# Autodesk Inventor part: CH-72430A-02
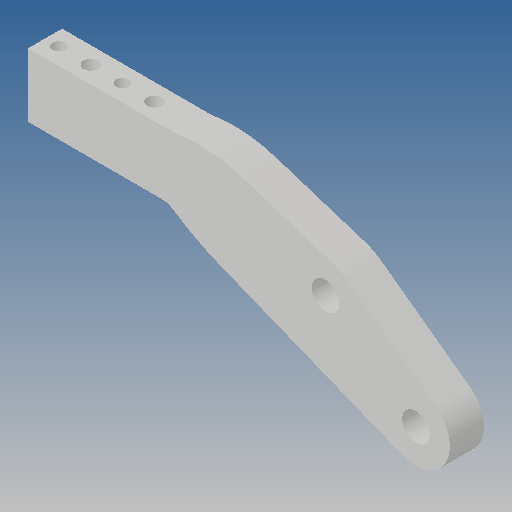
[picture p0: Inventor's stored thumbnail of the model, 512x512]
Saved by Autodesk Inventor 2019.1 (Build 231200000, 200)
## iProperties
Created: 2012-10
Part Number: CH-72430A-02
Material: Ogólny
Document SubType Name: Modeling
Designer: CADENGINEERING4
Density: 1 g/cm^3
Appearance: Domyślna
Author: CADENGINEERING4
Revision Number: ÈÎºÎ
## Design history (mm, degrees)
feature "ÇÐ³ý-À­Éì1"
node "Bryła1"
